// Mitsubishi GX Works2 project: FX2N PLC与LG变频器通信   PLC: FX2N/FX2NC

PROGRAM MAIN
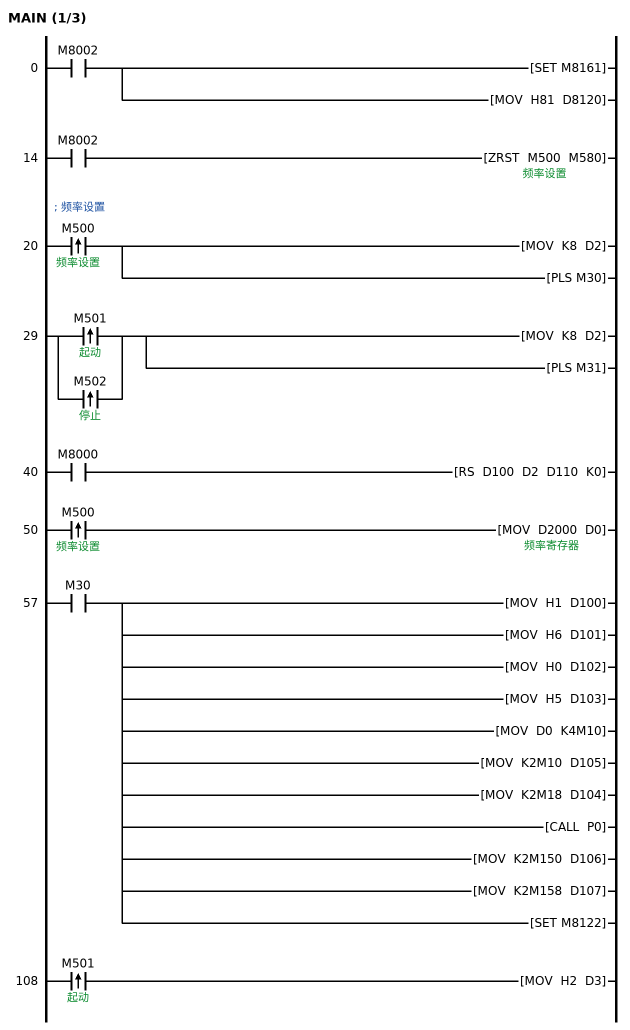
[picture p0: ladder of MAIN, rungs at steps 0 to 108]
0     LD      M8002
      SET     M8161
      MOV     H81 D8120
14    LD      M8002
      ZRST    M500 M580  ; 频率设置
; 频率设置
20    LDP     M500  ; 频率设置
      MOV     K8 D2
      PLS     M30
29    LDP     M501  ; 起动
      ORP     M502  ; 停止
      MOV     K8 D2
      PLS     M31
40    LD      M8000
      RS      D100 D2 D110 K0
50    LDP     M500  ; 频率设置
      MOV     D2000 D0  ; 频率寄存器
57    LD      M30
      MOV     H1 D100
      MOV     H6 D101
      MOV     H0 D102
      MOV     H5 D103
      MOV     D0 K4M10
      MOV     K2M10 D105
      MOV     K2M18 D104
      CALL    P0
      MOV     K2M150 D106
      MOV     K2M158 D107
      SET     M8122
108   LDP     M501  ; 起动
      MOV     H2 D3
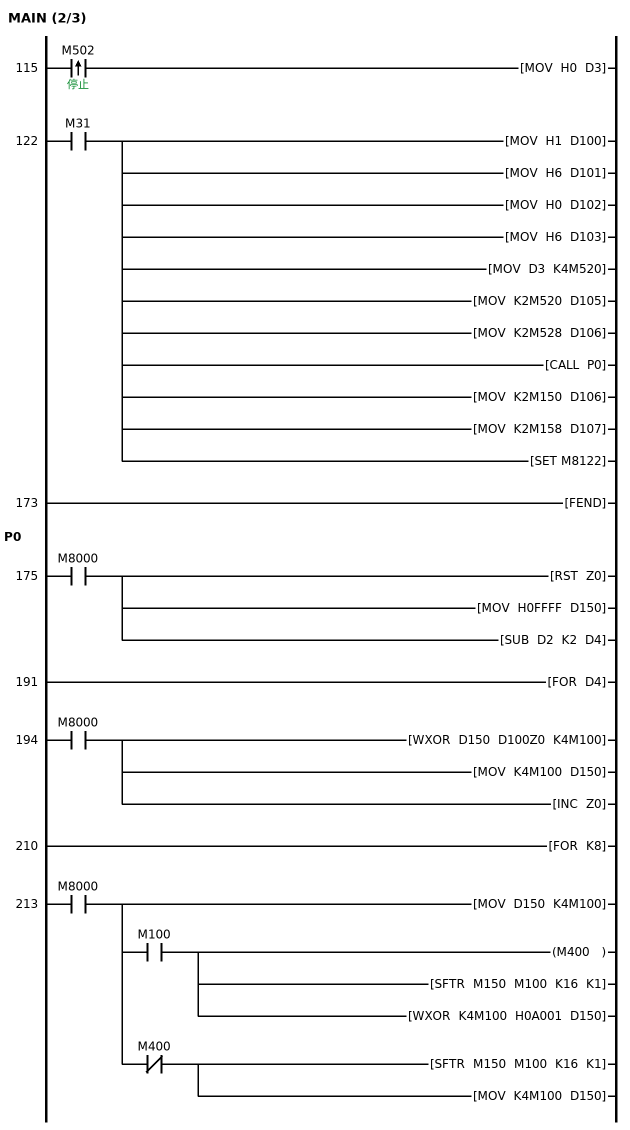
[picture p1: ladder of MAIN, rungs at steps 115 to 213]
115   LDP     M502  ; 停止
      MOV     H0 D3
122   LD      M31
      MOV     H1 D100
      MOV     H6 D101
      MOV     H0 D102
      MOV     H6 D103
      MOV     D3 K4M520
      MOV     K2M520 D105
      MOV     K2M528 D106
      CALL    P0
      MOV     K2M150 D106
      MOV     K2M158 D107
      SET     M8122
173   FEND
      P0
175   LD      M8000
      RST     Z0
      MOV     H0FFFF D150
      SUB     D2 K2 D4
191   FOR     D4
194   LD      M8000
      WXOR    D150 D100Z0 K4M100
      MOV     K4M100 D150
      INC     Z0
210   FOR     K8
213   LD      M8000
      MOV     D150 K4M100
      MPS
      AND     M100
      OUT     M400
      SFTR    M150 M100 K16 K1
      WXOR    K4M100 H0A001 D150
      MPP
      ANI     M400
      SFTR    M150 M100 K16 K1
      MOV     K4M100 D150
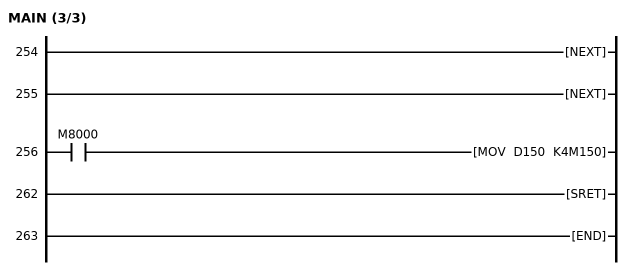
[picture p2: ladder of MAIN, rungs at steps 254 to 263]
254   NEXT
255   NEXT
256   LD      M8000
      MOV     D150 K4M150
262   SRET
263   END
END_PROGRAM
